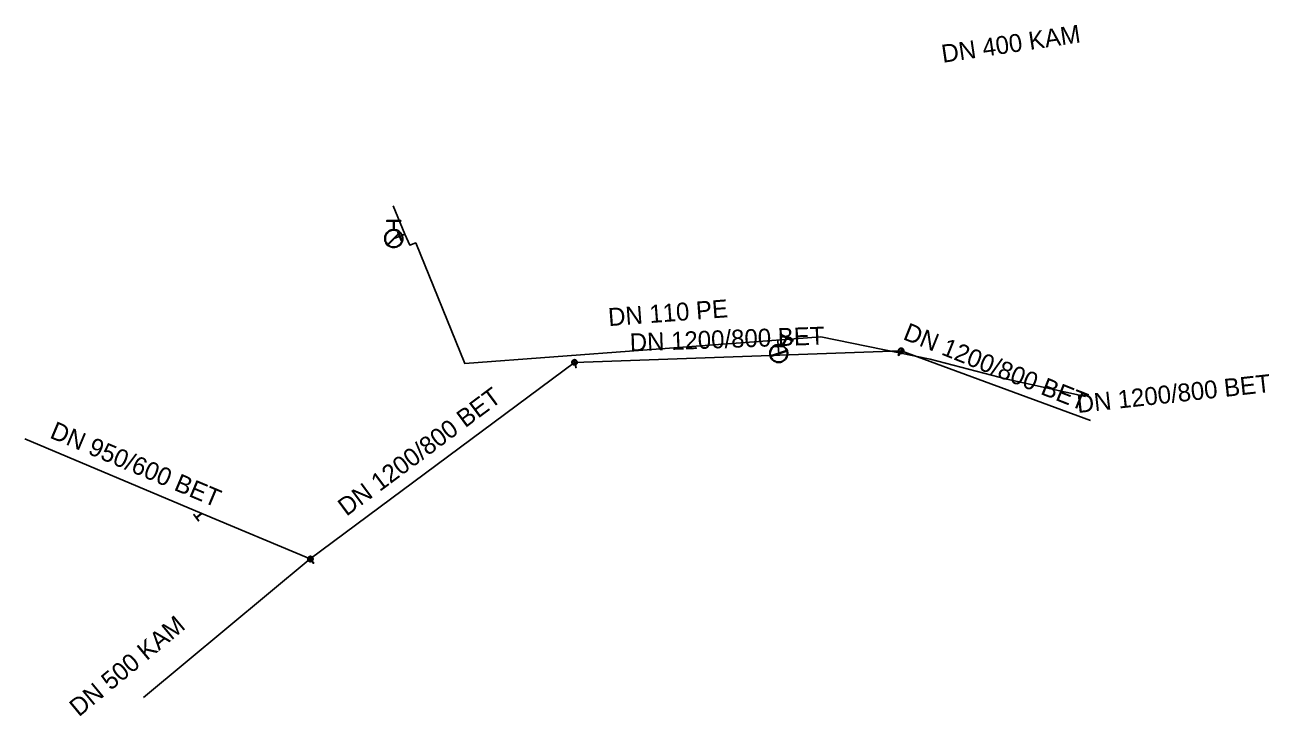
# Model space of a CAD drawing. Extents: x -839599 to -839460, y -1079386 to -1079309.
import ezdxf

# ---------------------------------------------------------------- set-up
doc = ezdxf.new("R2010")
doc.units = 0
for name, color, linetype in [('Hyd-odbočka', 7, 'Continuous'), ('Hyd-šoupě', 7, 'Continuous'), ('Hydrant', 7, 'Continuous'), ('Kanalizace - popis', 7, 'Continuous'), ('Odlehčovací stoka', 7, 'Continuous'), ('Roz-řad', 7, 'Continuous'), ('Roz-řad-popis základní', 7, 'Continuous'), ('Vysazená odbočka', 7, 'Continuous'), ('Šachta kanalizační', 7, 'Continuous')]:
    doc.layers.add(name, color=color, linetype=linetype)

msp = doc.modelspace()

# ---------------------------------------------------------------- linework, layer by layer
at = {"layer": 'Hyd-odbočka'}
for p, q in [((-839557.27, -1079332.27), (-839557.92, -1079332.5)), ((-839556.68, -1079332.03), (-839557.27, -1079332.27)), ((-839515.13, -1079343.84), (-839515.08, -1079344.51)), ((-839515.08, -1079344.51), (-839515.03, -1079345.32))]:
    msp.add_line(p, q, dxfattribs=at)
at = {"layer": 'Hyd-šoupě'}
for points in [[(-839557.09, -1079332.73), (-839557.48, -1079331.81), (-839557.46, -1079331.8), (-839557.06, -1079332.72), (-839557.09, -1079332.73)], [(-839514.58, -1079344.53), (-839515.58, -1079344.53), (-839515.58, -1079344.5), (-839514.58, -1079344.5), (-839514.58, -1079344.53)]]:
    msp.add_lwpolyline(points, dxfattribs=at)
at = {"layer": 'Hydrant'}
for points in [[(-839557.95, -1079331.5), (-839557.95, -1079330.57), (-839558.7, -1079330.57), (-839558.7, -1079330.5), (-839557.14, -1079330.5), (-839557.14, -1079330.57), (-839557.89, -1079330.57), (-839557.89, -1079331.5)], [(-839558.61, -1079333.15), (-839557.28, -1079331.82)], [(-839557.24, -1079331.86), (-839558.56, -1079333.19)], [(-839514.61, -1079344.41), (-839514.19, -1079343.57), (-839514.86, -1079343.23), (-839514.83, -1079343.18), (-839513.43, -1079343.88), (-839513.46, -1079343.93), (-839514.13, -1079343.6), (-839514.55, -1079344.44)], [(-839515.93, -1079345.58), (-839514.15, -1079344.99)], [(-839514.13, -1079345.05), (-839515.91, -1079345.64)]]:
    msp.add_lwpolyline(points, dxfattribs=at)
for points in [[(-839557.89, -1079331.5), (-839557.65, -1079331.51), (-839557.43, -1079331.63), (-839557.19, -1079331.76), (-839557.06, -1079332), (-839556.92, -1079332.24), (-839556.92, -1079332.5), (-839556.92, -1079332.76), (-839557.05, -1079333), (-839557.18, -1079333.24), (-839557.42, -1079333.37), (-839557.66, -1079333.5), (-839557.92, -1079333.5), (-839558.18, -1079333.5), (-839558.42, -1079333.37), (-839558.66, -1079333.24), (-839558.79, -1079333), (-839558.92, -1079332.76), (-839558.92, -1079332.5), (-839558.92, -1079332.24), (-839558.79, -1079332), (-839558.65, -1079331.76), (-839558.41, -1079331.63), (-839558.19, -1079331.51), (-839557.95, -1079331.5)], [(-839557.28, -1079331.82), (-839557.36, -1079331.74), (-839557.46, -1079331.69), (-839557.68, -1079331.57), (-839557.92, -1079331.57), (-839558.16, -1079331.57), (-839558.38, -1079331.69), (-839558.61, -1079331.81), (-839558.73, -1079332.03), (-839558.86, -1079332.26), (-839558.86, -1079332.5), (-839558.86, -1079332.75), (-839558.73, -1079332.97), (-839558.68, -1079333.07), (-839558.61, -1079333.15)], [(-839558.56, -1079333.19), (-839558.49, -1079333.26), (-839558.39, -1079333.32), (-839558.17, -1079333.44), (-839557.92, -1079333.44), (-839557.68, -1079333.44), (-839557.45, -1079333.32), (-839557.23, -1079333.19), (-839557.11, -1079332.97), (-839556.98, -1079332.75), (-839556.98, -1079332.5), (-839556.98, -1079332.26), (-839557.11, -1079332.03), (-839557.17, -1079331.94), (-839557.24, -1079331.86)], [(-839514.55, -1079344.44), (-839514.35, -1079344.55), (-839514.2, -1079344.76), (-839514.04, -1079344.98), (-839514.03, -1079345.25), (-839514.02, -1079345.53), (-839514.13, -1079345.76), (-839514.25, -1079346), (-839514.48, -1079346.15), (-839514.7, -1079346.3), (-839514.97, -1079346.32), (-839515.24, -1079346.33), (-839515.48, -1079346.21), (-839515.71, -1079346.09), (-839515.86, -1079345.87), (-839516.02, -1079345.64), (-839516.03, -1079345.37), (-839516.04, -1079345.1), (-839515.92, -1079344.87), (-839515.81, -1079344.63), (-839515.58, -1079344.48), (-839515.35, -1079344.33), (-839515.08, -1079344.32), (-839514.83, -1079344.31), (-839514.61, -1079344.41)], [(-839514.15, -1079344.99), (-839514.19, -1079344.89), (-839514.25, -1079344.79), (-839514.4, -1079344.58), (-839514.61, -1079344.48), (-839514.82, -1079344.37), (-839515.08, -1079344.38), (-839515.33, -1079344.39), (-839515.54, -1079344.53), (-839515.76, -1079344.68), (-839515.87, -1079344.9), (-839515.98, -1079345.11), (-839515.96, -1079345.37), (-839515.96, -1079345.48), (-839515.93, -1079345.58)], [(-839515.91, -1079345.64), (-839515.87, -1079345.74), (-839515.81, -1079345.83), (-839515.67, -1079346.04), (-839515.45, -1079346.15), (-839515.23, -1079346.26), (-839514.97, -1079346.25), (-839514.72, -1079346.24), (-839514.51, -1079346.1), (-839514.3, -1079345.95), (-839514.19, -1079345.74), (-839514.08, -1079345.52), (-839514.09, -1079345.26), (-839514.1, -1079345.15), (-839514.13, -1079345.05)]]:
    msp.add_open_spline(points, degree=3, dxfattribs=at)
at = {"layer": 'Odlehčovací stoka'}
for p, q in [((-839537.78, -1079346.31), (-839501.39, -1079345.01)), ((-839501.39, -1079345.01), (-839480.28, -1079352.79)), ((-839567.22, -1079368.23), (-839537.78, -1079346.31))]:
    msp.add_line(p, q, dxfattribs=at)
for points in [[(-839599.02, -1079354.85), (-839579.29, -1079363.15), (-839567.22, -1079368.23)], [(-839585.82, -1079383.67), (-839567.22, -1079368.23)]]:
    msp.add_lwpolyline(points, dxfattribs=at)
at = {"layer": 'Roz-řad'}
msp.add_lwpolyline([(-839557.98, -1079328.86), (-839556.68, -1079332.03), (-839556.14, -1079333.23), (-839555.48, -1079332.99), (-839550, -1079346.44), (-839510.34, -1079343.47), (-839498.16, -1079345.94), (-839489.62, -1079348.19), (-839480.83, -1079350.12)], dxfattribs=at)
at = {"layer": 'Vysazená odbočka'}
msp.add_lwpolyline([(-839579.3, -1079363.17), (-839579.9, -1079363.63), (-839579.65, -1079363.97), (-839579.67, -1079363.99), (-839580.2, -1079363.29), (-839580.18, -1079363.27), (-839579.92, -1079363.61), (-839579.31, -1079363.14), (-839579.29, -1079363.15), (-839579.3, -1079363.17)], dxfattribs=at)
at = {"layer": 'Šachta kanalizační'}
for points in [[(-839501.53, -1079345.21), (-839501.29, -1079344.78)], [(-839501.24, -1079344.81), (-839501.49, -1079345.24)], [(-839537.74, -1079346.55), (-839537.88, -1079346.08)], [(-839537.83, -1079346.06), (-839537.69, -1079346.54)], [(-839537.67, -1079346.59), (-839537.59, -1079346.87), (-839537.64, -1079346.89), (-839537.72, -1079346.6)], [(-839501.51, -1079345.28), (-839501.66, -1079345.54), (-839501.71, -1079345.52), (-839501.56, -1079345.26)], [(-839567.09, -1079368.45), (-839567.38, -1079368.05)], [(-839567.34, -1079368.02), (-839567.05, -1079368.42)], [(-839567.02, -1079368.46), (-839566.84, -1079368.7), (-839566.88, -1079368.73), (-839567.06, -1079368.49)]]:
    msp.add_lwpolyline(points, dxfattribs=at)
for points in [[(-839501.56, -1079345.26), (-839501.61, -1079345.22), (-839501.65, -1079345.16), (-839501.69, -1079345.09), (-839501.69, -1079345.01), (-839501.69, -1079344.93), (-839501.65, -1079344.86), (-839501.61, -1079344.79), (-839501.54, -1079344.75), (-839501.47, -1079344.71), (-839501.39, -1079344.71), (-839501.31, -1079344.71), (-839501.24, -1079344.75), (-839501.17, -1079344.79), (-839501.13, -1079344.86), (-839501.09, -1079344.92), (-839501.09, -1079345.01), (-839501.09, -1079345.09), (-839501.13, -1079345.16), (-839501.17, -1079345.23), (-839501.24, -1079345.27), (-839501.31, -1079345.31), (-839501.39, -1079345.31), (-839501.46, -1079345.31), (-839501.51, -1079345.28)], [(-839501.29, -1079344.78), (-839501.33, -1079344.76), (-839501.39, -1079344.76), (-839501.46, -1079344.76), (-839501.51, -1079344.79), (-839501.57, -1079344.83), (-839501.61, -1079344.89), (-839501.64, -1079344.94), (-839501.64, -1079345.01), (-839501.64, -1079345.08), (-839501.6, -1079345.14), (-839501.57, -1079345.19), (-839501.53, -1079345.21)], [(-839501.49, -1079345.24), (-839501.44, -1079345.26), (-839501.39, -1079345.26), (-839501.32, -1079345.26), (-839501.26, -1079345.23), (-839501.2, -1079345.19), (-839501.17, -1079345.13), (-839501.14, -1079345.08), (-839501.14, -1079345.01), (-839501.14, -1079344.94), (-839501.17, -1079344.88), (-839501.2, -1079344.83), (-839501.24, -1079344.81)], [(-839537.72, -1079346.6), (-839537.78, -1079346.61), (-839537.85, -1079346.6), (-839537.93, -1079346.58), (-839537.99, -1079346.52), (-839538.05, -1079346.47), (-839538.07, -1079346.39), (-839538.09, -1079346.32), (-839538.08, -1079346.24), (-839538.06, -1079346.16), (-839538, -1079346.1), (-839537.94, -1079346.04), (-839537.87, -1079346.02), (-839537.8, -1079346), (-839537.72, -1079346.01), (-839537.64, -1079346.03), (-839537.58, -1079346.09), (-839537.52, -1079346.15), (-839537.5, -1079346.22), (-839537.47, -1079346.3), (-839537.49, -1079346.38), (-839537.51, -1079346.46), (-839537.57, -1079346.51), (-839537.62, -1079346.57), (-839537.67, -1079346.59)], [(-839537.88, -1079346.08), (-839537.92, -1079346.09), (-839537.97, -1079346.13), (-839538.01, -1079346.18), (-839538.03, -1079346.25), (-839538.04, -1079346.32), (-839538.02, -1079346.38), (-839538.01, -1079346.44), (-839537.96, -1079346.49), (-839537.91, -1079346.54), (-839537.84, -1079346.55), (-839537.78, -1079346.56), (-839537.74, -1079346.55)], [(-839537.69, -1079346.54), (-839537.64, -1079346.52), (-839537.6, -1079346.48), (-839537.55, -1079346.43), (-839537.54, -1079346.36), (-839537.53, -1079346.3), (-839537.54, -1079346.24), (-839537.56, -1079346.17), (-839537.61, -1079346.13), (-839537.66, -1079346.08), (-839537.73, -1079346.06), (-839537.79, -1079346.05), (-839537.83, -1079346.06)], [(-839567.06, -1079368.49), (-839567.11, -1079368.52), (-839567.18, -1079368.53), (-839567.26, -1079368.54), (-839567.34, -1079368.51), (-839567.41, -1079368.47), (-839567.46, -1079368.41), (-839567.5, -1079368.35), (-839567.51, -1079368.27), (-839567.52, -1079368.18), (-839567.49, -1079368.11), (-839567.46, -1079368.04), (-839567.39, -1079367.99), (-839567.33, -1079367.95), (-839567.25, -1079367.93), (-839567.17, -1079367.92), (-839567.1, -1079367.96), (-839567.02, -1079367.99), (-839566.98, -1079368.05), (-839566.93, -1079368.11), (-839566.92, -1079368.2), (-839566.91, -1079368.28), (-839566.94, -1079368.35), (-839566.97, -1079368.42), (-839567.02, -1079368.46)], [(-839567.38, -1079368.05), (-839567.42, -1079368.08), (-839567.44, -1079368.13), (-839567.47, -1079368.19), (-839567.46, -1079368.26), (-839567.46, -1079368.33), (-839567.42, -1079368.38), (-839567.38, -1079368.43), (-839567.32, -1079368.46), (-839567.25, -1079368.49), (-839567.19, -1079368.48), (-839567.13, -1079368.47), (-839567.09, -1079368.45)], [(-839567.05, -1079368.42), (-839567.01, -1079368.38), (-839566.99, -1079368.33), (-839566.96, -1079368.27), (-839566.97, -1079368.2), (-839566.98, -1079368.13), (-839567.02, -1079368.08), (-839567.05, -1079368.03), (-839567.12, -1079368), (-839567.18, -1079367.97), (-839567.25, -1079367.98), (-839567.3, -1079367.99), (-839567.34, -1079368.02)]]:
    msp.add_open_spline(points, degree=3, dxfattribs=at)

# ---------------------------------------------------------------- texts
at = {"layer": 'Kanalizace - popis'}
for s, rotation, p in [('DN 400 KAM', 8.4375, (-839496.74, -1079312.91)), ('DN 1200/800 BET', 2.0425, (-839531.59, -1079345.09)), ('DN 1200/800 BET', 338.2647, (-839501.29, -1079343.7)), ('DN 1200/800 BET', 6.2429, (-839481.71, -1079351.96)), ('DN 1200/800 BET', 36.683, (-839563.19, -1079363.53)), ('DN 950/600 BET', 337.1802, (-839596.36, -1079354.68)), ('DN 500 KAM', 39.6861, (-839593.01, -1079385.9))]:
    msp.add_text(s, height=2, rotation=rotation, dxfattribs=at).set_placement(p)
at = {"layer": 'Roz-řad-popis základní'}
msp.add_text('DN 110 PE', height=2, rotation=4.2864, dxfattribs=at).set_placement((-839533.96, -1079342.27))

doc.saveas('drawing.dxf')
